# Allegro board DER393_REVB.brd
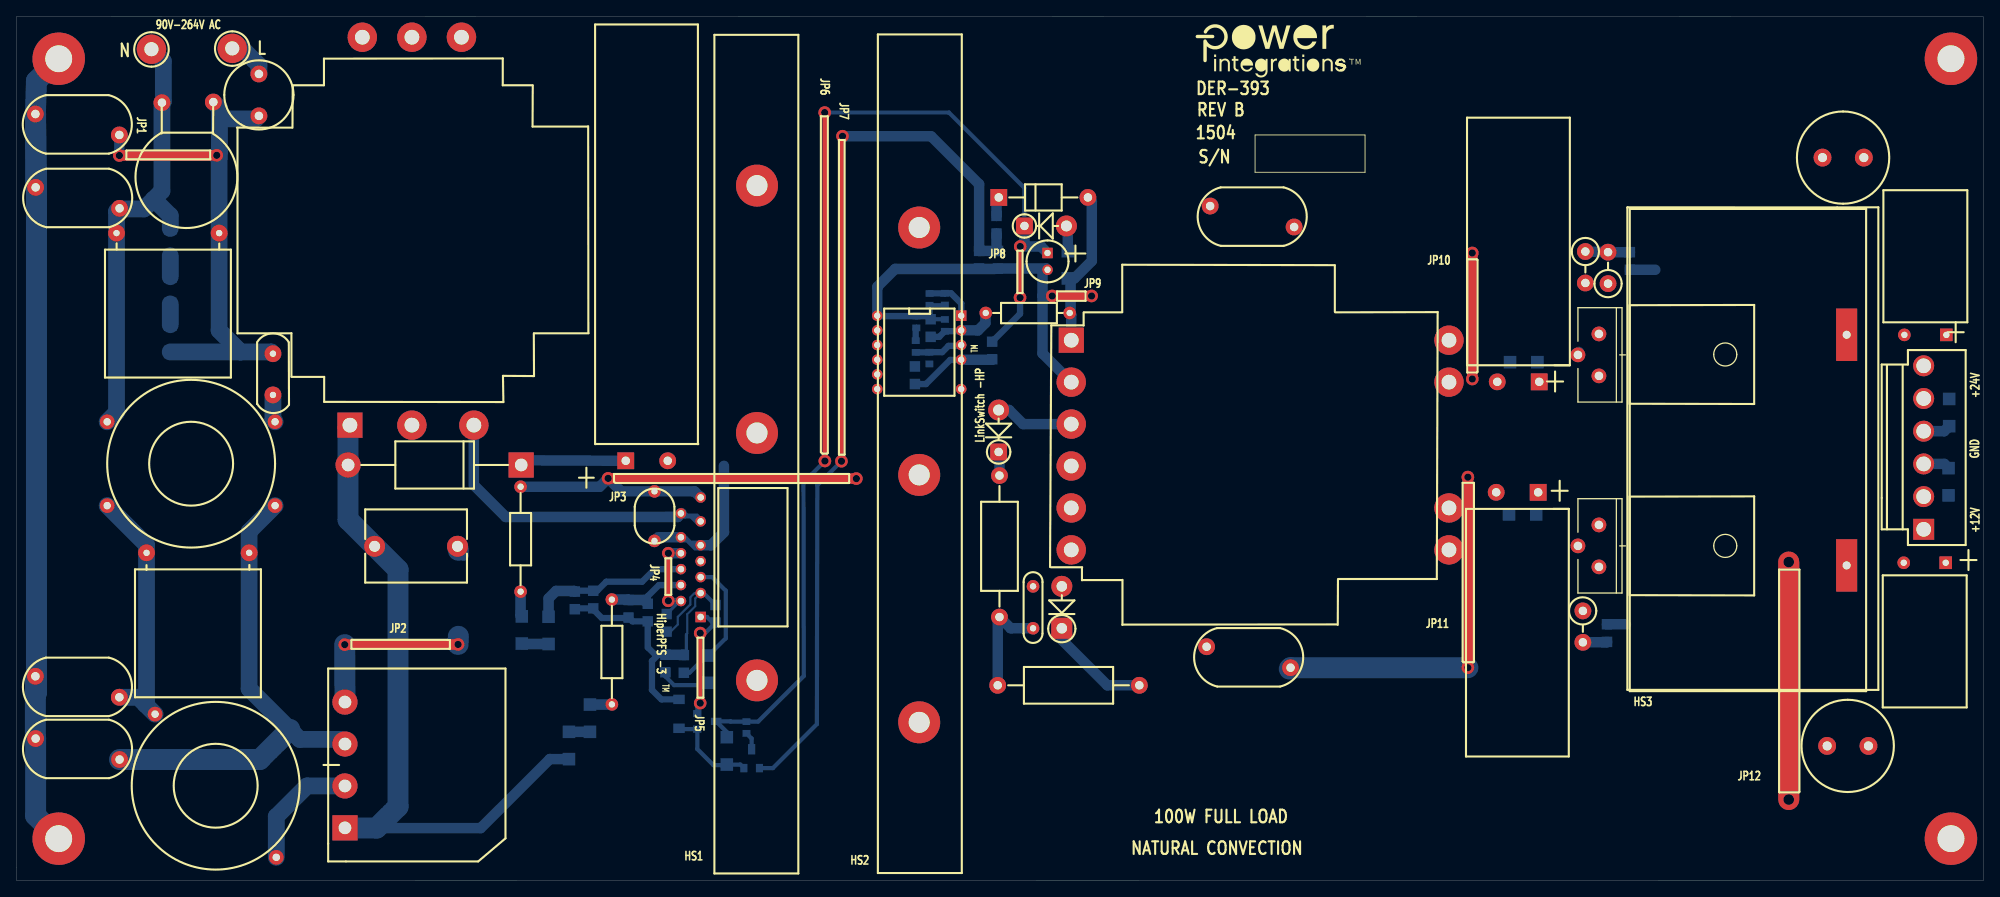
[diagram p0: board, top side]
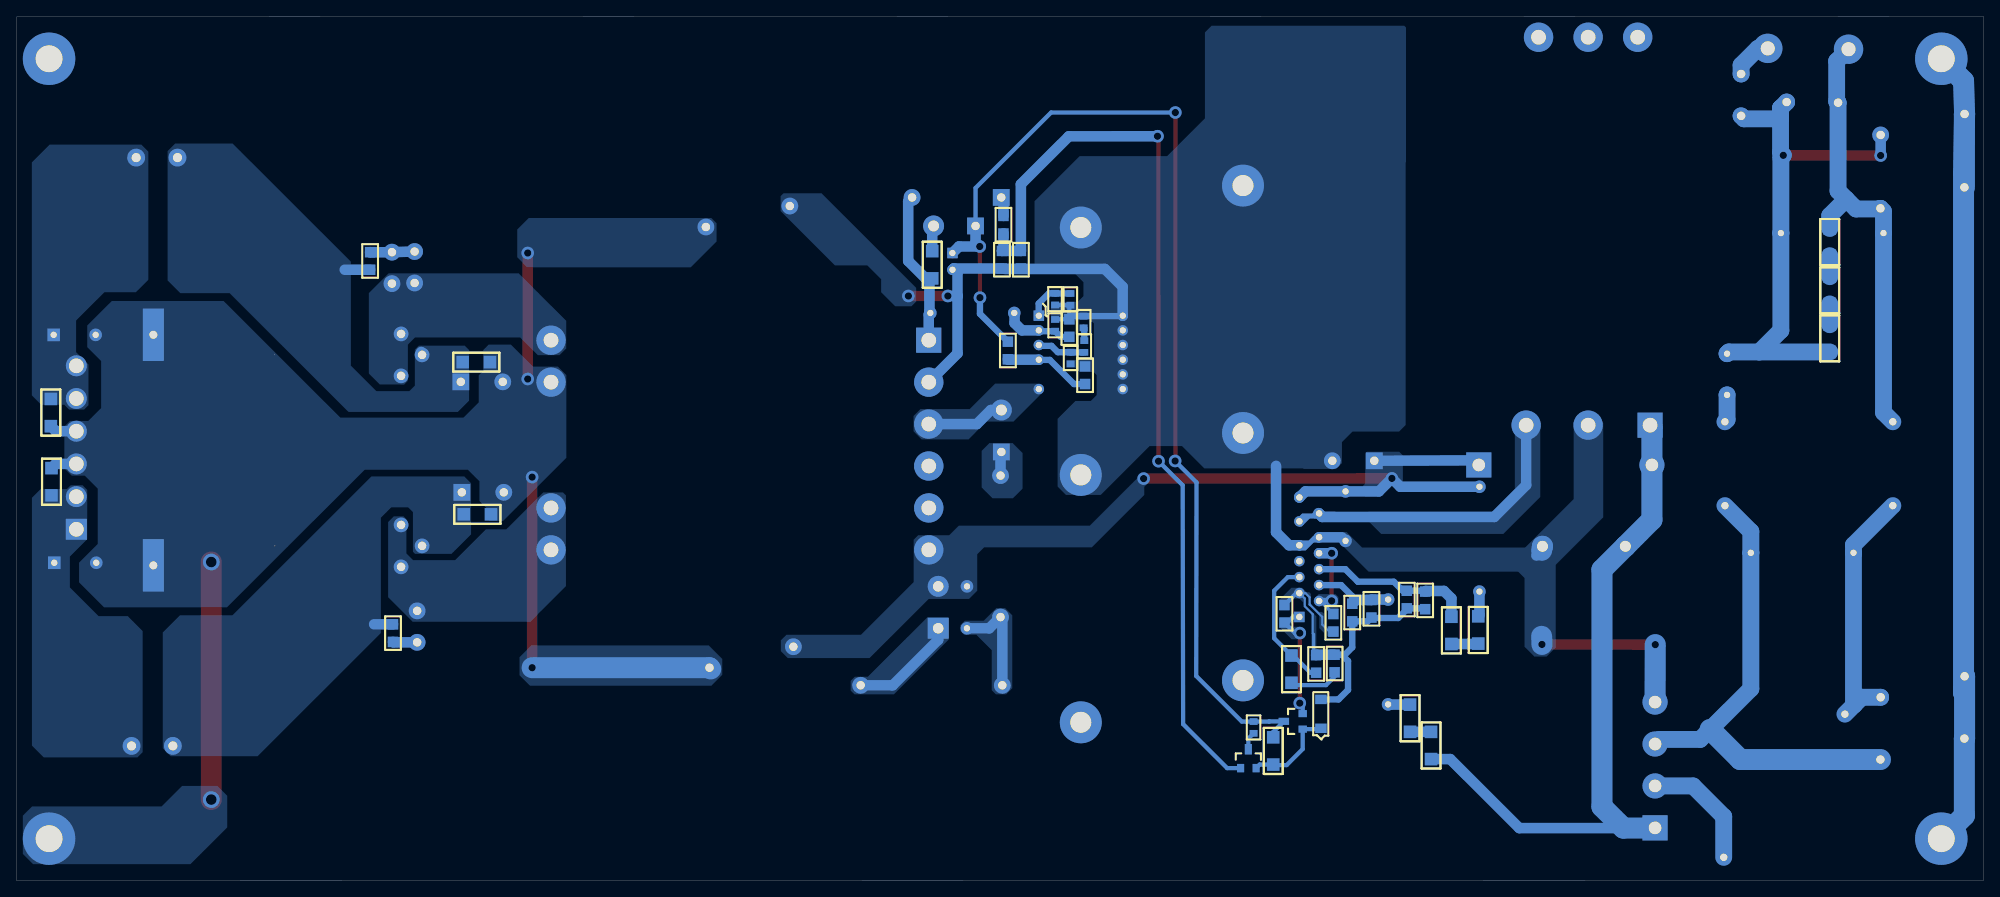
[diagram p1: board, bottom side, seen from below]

Outline 238.07 x 104.67 mm; copper layers: TOP, BOTTOM. Coordinates in mm from the lower left corner of the outline.
Outline path: 0,104.67 238.07,104.62 238.07,0 0,0.03 0,104.67

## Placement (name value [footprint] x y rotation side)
BR1  RS605  [PI_DAX_BRIDGE_RS605_H]  39.75 6.38 90 top
C1  1 nF  [PINPYCAPRAD540X290LS400040]  12.45 90.32 180 top
C2  1 nF  [PINPYCAPRAD540X290LS400040]  2.31 83.97 0 top
C3  220 nF  [PINPCAPRAD550X395490030HORZ]  24.55 78.46 180 top
C4  2.2 nF  [PINPYCAPRAD540X290LS400040]  12.47 14.66 180 top
C5  2.2 nF  [PINPYCAPRAD540X290LS400040]  2.29 24.74 0 top
C6  220 nF  [PINPCAPRAD550X395490030HORZ]  28.18 39.73 180 top
C7  470 nF  [PI_NP_CAPRAD512X345LS394D040]  43.35 40.49 0 bottom
C8  1 uF  [PISMC0805]  84.61 31.24 90 bottom
C9  1 uF  [PISMC0805]  78.69 32.28 270 bottom
C10  470 pF  [PISMC0805]  76.4 33.53 270 bottom
C11  100 nF  [PISMC0805]  80.77 25.17 90 bottom
C12  1 uF  [PISMC0805]  78.54 25.22 90 bottom
C13  10 nF  [PI_NP_CAP250X200LS170D030]  77.22 46.3 270 top
C14  470 pF  [PISMC0805]  69.8 35.1 270 bottom
C15  82 uF  [PI_PCAP_D500LS200_040_2000H]  73.74 50.85 0 bottom
C16  2.2 nF  [PINPCAPRAD350X100200030]  123.04 35.64 270 top
C17  1000 pF  [PISMC0603]  112.37 71.15 270 bottom
C18  100 pF  [PISMC0603]  110.49 64.01 270 bottom
C19  100 nF  [PISMC0603]  108.92 66.95 90 bottom
C20  4.7 uF  [PISMC0805]  108.74 60.15 90 bottom
C21  22  uF  [PIPOLCAPCLYD200LS80030]  124.79 76.02 270 top
C22  *  [PISMC0805]  110.64 65.86 90 bottom
C23  100 nF  [PISMC0805]  118.8 76.28 270 bottom
C24  2.2 nF  [PINPYCAPRAD540X290LS400040]  144.04 28.32 0 top
C25  2.2 nF  [PINPYCAPRAD540X290LS400040]  144.48 81.71 0 top
C26  470 pF  [PISMC0805]  195.28 76.12 270 bottom
C27  1 uF  [PISMC1206]  184.07 62.8 180 bottom
C28  1200 uF  [PIPOLCAPCLYD500LS2000401200LH]  184.3 60.41 180 top
C29  330 uF  [PIPOLCAPCLYD395X630LS200030H]  233.58 66.1 180 top
C30  470 pF  [PISMC0805]  192.51 28.91 90 bottom
C31  1 uF  [PISMC1206]  183.95 44.36 180 bottom
C32  1800 uF  [PIPOLCAPCLYD500LS2000401200LH]  184.18 47.03 180 bottom
C33  470 uF  [PIPOLCAPCLYD395X630LS200030H]  233.5 38.49 180 bottom
D1  1N5408-T  [PIDAX800X225060DO15DO201AD]  61.09 50.34 180 top
D2  FR107-B  [PIDV200X110X040DO41#2]  118.87 51.92 90 top
D3  FR107-B  [PIDV200X110X040DO41#2]  122 79.3 0 top
D4  STPS10150CT  [PIDVTO2203VF1H]  192.04 63.63 270 top
D5  STPS30100ST  [PIDVTO2203VF1H#2]  191.83 40.61 270 top
D6  FR107-B  [PIDV200X110X040DO41]  118.88 82.75 0 top
F1  2 A  [PI_TR5_SUBMIN_FUSE]  29.34 97.71 270 top
HS1  HEATSINK,FAB, W/PINS, PI CUST  [PI_HS_PFS3_LNKHP110W]  89.55 84.16 270 top
HS2  HEATSINK,FAB, W/PINS, PI CUST  [PI_HS_PFS3_LNKHP110W]  109.33 19.19 90 top
HS3  HEATSINK, FAB,W/EYELET, PI CUST  [PI_HS_DIODES_SEC_DER393]  223.88 81.36 180 top
J1  CON6  [PI_HDR_6PIN_LOCK]  230.84 42.54 0 top
L1  10mH  [PI_IND_4P_690X512LS300X200D055]  21.13 50.5 0 top
L2  PQ38  [PI_BOBBIN_PQ38_6P]  47.85 78.66 90 top
L3  470uH  [PI_2P_700X400D055_HORIZ]  24.1 11.48 336.8 top
L4  1.0 uH  [PI_CHOKE_TOK441LS197D043]  218.59 87.58 0 top
L5  1.0 uH  [PI_CHOKE_TOK441LS197D043]  219.15 16.31 0 top
MTG_HOLE4  No 4  [PIMTGHOLE4]  5.11 5.07 0 top
MTG_HOLE5  No 4  [PIMTGHOLE4]  234.14 99.56 0 top
MTG_HOLE6  No 4  [PIMTGHOLE4]  5.11 99.56 0 top
MTG_HOLE7  No 4  [PIMTGHOLE4]  234.14 5.07 0 top
NOREF  -  []  -149.29 55.89 0 top
NOREF#2  -  []  238.07 0 90 top
NOREF#3  -  []  -227.1 -143.13 0 top
NOREF#4  -  []  0 0.03 0 top
NOREF#5  -  []  142.72 103.71 0 top
Q1  MMBT4401LT1G  [PISMSOT23132]  82.4 20.22 90 bottom
Q2  MMBT4401LT1G  [PISMSOT23132]  88.04 13.61 180 bottom
R1  620 k  [PISMR1206]  18.61 64.03 90 bottom
R2  620 k  [PISMR1206]  18.61 69.85 90 bottom
R3  620 k  [PISMR1206]  18.61 75.69 90 bottom
R4  6.2 M  [PISMR1206]  66.87 14.71 90 bottom
R5  6.2 M  [PISMR1206]  69.41 18.01 90 bottom
R6  3.74 M  [PI14WRESD100LS500D030]  72.06 21.34 90 top
R7  162 k  [PISMR0805]  74.08 33.99 270 bottom
R8  10 k  [PISMR1206]  85.97 17.35 270 bottom
R9  30.1 k  [PISMR1206]  83.76 27.25 270 bottom
R10  3.74 M  [PI14WVRESD100LS100D030]  61.01 47.7 270 top
R11  6.2 M  [PISMR1206]  61.15 32 270 bottom
R12  6.2 M  [PISMR1206]  64.4 28.65 90 bottom
R13  162 k  [PISMR0805]  67.58 35 270 bottom
R14  1 k  [PI12WRESD180LS675D040]  135.9 23.65 180 top
R15  4.7  [PI12WRESD180LS675D040]  118.97 31.92 90 top
R16  124 k  [PISMR0603]  110.52 71.12 270 bottom
R17  100 k  [PISMR0603]  108.84 63.98 90 bottom
R18  6.8 k  [PISMR0805]  118.08 63.14 90 bottom
R19  3.3  [PISMR1206]  127.24 76.25 270 bottom
R20  61.9 k  [PI14WRESD100LS400D030]  127.47 68.76 180 top
R21  8.66 k  [PISMR0603]  112.37 66.55 90 bottom
R22  2 k  [PISMR0805]  118.62 80.52 270 bottom
R23  330 k  [PISMR0805]  116.51 76.28 270 bottom
R24  2 k  [PISMR0603]  88.34 19.25 270 bottom
R25  30  [PI12WVRESD180LS150D040]  192.63 72.31 90 top
R26  30  [PI12WVRESD180LS150D040]  189.89 76.2 270 top
R27  15  [PI12WVRESD180LS150D040]  189.59 32.66 270 top
R28  20 k  [PISMR1206]  233.92 58.34 270 bottom
R29  24 k  [PISMR1206]  233.85 49.96 270 bottom
RT1  2.5  [PI_RAD150X300LS200D030]  31.04 63.83 270 top
RV1  320 Vac  [PI_RAD450X550LS300D040_H]  24.68 94.67 180 top
T1  XXXX  [PI_BOBBIN_PQ3812_10P_1800LS]  127.66 40.06 0 top
TP1  CON1  [PITPKEYSTONE125X125]  26.11 100.81 0 top
TP2  CON1  [PITPKEYSTONE125X125]  16.33 100.71 0 top
U1  PFS7524L  [PIICLBENDESIPLG]  82.8 31.93 270 top
U2  LNK6777V  [PI_IC_EDIP_11-12P]  114.34 68.43 270 top
VR1  MMSZ4700T1G  [PI_SM_SOD-123_12]  80.19 18.44 90 bottom
VR2  P6KE150A  [PIDV200X140X050DO15DO204AC]  126.52 30.56 90 top

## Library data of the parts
BR1 = DIODE BRIDGE_1234: alternate symbols: (pi_dax_bridge_rs605_h)
C1 C2 C4 C5 C24 C25 = CAP NP: alternate symbols: (pinpycaprad540x290ls400040h)
C3 C6 = CAP NP: alternate symbols: (pinpcaprad550x395490030horz)
C7-C12 C14 C17-C20 C22 C23 C27 C31 = CAP NP
C13 = CAP NP: tolerance: 20
C15 = CAP POL: alternate symbols: (pi_pcap_d500ls200_040_2000h)
C16 C26 C30 = CAP NP: tolerance: 10
C21 = CAP POL: alternate symbols: (pipolcapclyd200ls80030h)
C28 C32 = CAP POL: alternate symbols: (pipolcapclyd500ls2000401200lh); tolerance: 20
C29 C33 = CAP POL: alternate symbols: (pipolcapclyd395x630ls200030h); tolerance: 20
D1 = DIODE: alternate symbols: (pidax800x225060do15do201ad,pidv300x200x060do14wbead)
D2 D3 D6 = DIODE: alternate symbols: (pidax475x125040do41,pidv200x110x040do41wbead,pidax390x125040do41)
D4 = DS_DUAL_CK_AKA: alternate symbols: (pidvto2203,pidvto2203vf1,pidvto2203vf1h)
D5 = DS_DUAL_CK_A_AC: alternate symbols: (pidvto2203vf1)
F1 = FUSE
HS1 = HS-PI_CUSTOM_0
HS2 = HS-PI_CUSTOM_1
HS3 = HS-PI_CUSTOM2
J1 = CON6
L1 = INDUCTOR_4P_revD: alternate symbols: (pi_4p_700x400d055_horiz)
L2 = BPQ38/6P/GENERIC
L3 = INDUCTOR
L4 L5 = INDUCTOR: tolerance: 0.2
MTG_HOLE4-MTG_HOLE7 = MTG_HOLE_6-32
Q1 Q2 = NPN_BEC
R1-R5 R7-R9 R11-R13 R16-R19 R21-R24 R28 R29 = R
R6 R10 R20 = R: alternate symbols: (pi14wvresd100ls200d030,pi14wresd100ls400d030,pi14wresd100ls500d030)
R14 R25-R27 = R: alternate symbols: (pi12wvresd180ls200d040,pi12wvresd180ls250d040,pi12wresd180ls675d040); tolerance: 5%
R15 = R: alternate symbols: (pi12wvresd180ls200d040,pi12wvresd180ls250d040,pi12wresd180ls675d040)
RT1 = THERMISTOR
RV1 = VARISTOR
T1 = BPQ3812/10P/GENERIC
TP1 TP2 = TESTPOINT
U1 = DEV_HIPERPFS-3-eSIP-16C
U2 = DEV_LNKHP_eDIP_eSOP
VR1 = DIODE_ZENER
VR2 = DIODE_ZENER: alternate symbols: (pidax550x140050do15do204ac)

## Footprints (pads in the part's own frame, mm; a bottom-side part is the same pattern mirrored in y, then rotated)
PI12WRESD180LS675D040
  round 2.032 hole 1.016: 1(0,0) 2(17.145,0)
PI12WVRESD180LS150D040
  round 2.032 hole 1.016: 1(0,0) 2(3.81,0)
PI14WRESD100LS400D030
  round 1.524 hole 0.762: 1(0,0) 2(10.16,0)
PI14WRESD100LS500D030
  round 1.524 hole 0.762: 1(0,0) 2(12.7,0)
PI14WVRESD100LS100D030
  round 1.524 hole 0.762: 1(0,0) 2(12.7,0)
PI_2P_700X400D055_HORIZ
  round 1.778 hole 0.889: 1(-10.16,5.08) 2(10.16,-5.08)
PI_BOBBIN_PQ38_6P
  rect 3.048x3.048 hole 1.778: 1(-23.5,7.501)
  round 3.556 hole 1.778: 2(-23.498,0) 3(-23.498,-7.501) 4(23.5,-5.999) 5(23.5,0) 6(23.5,5.999)
PI_BOBBIN_PQ3812_10P_1800LS
  rect 3.048x3.048 hole 1.778: 1(0,25.4)
  round 3.556 hole 1.778: 2(0,20.32) 3(0,15.24) 4(0,10.16) 5(0,5.08) 6(0,0) 7(45.72,0) 8(45.72,5.08) 9(45.72,20.32) 10(45.72,25.4)
PI_CHOKE_TOK441LS197D043
  round 2.159 hole 1.092: 1(0,0) 2(5.001,0)
PI_DAX_BRIDGE_RS605_H
  rect 3.048x3.048 hole 1.524: 1(0,0)
  round 3.048 hole 1.524: 2(5.08,0) 3(10.16,0) 4(15.24,0)
PI_HDR_6PIN_LOCK
  rect 2.54x2.54 hole 1.778: 1(0,0)
  round 2.54 hole 1.778: 2(0,3.962) 3(0,7.925) 4(0,11.887) 5(0,15.85) 6(0,19.812)
PI_HS_DIODES_SEC_DER393
  rect 2.54x6.35 hole 0.965: 1(2.362,43.18) 2(2.362,15.24)
PI_HS_PFS3_LNKHP110W
  round 5.08 hole 2.54: 1(-0.025,0.076) 2(29.947,0.076) 3(59.919,0.076)
PI_IC_EDIP_11-12P
  rect 1.27x1.27 hole 0.762: 1(0,0)
  round 1.27 hole 0.762: 2(1.778,0) 3(3.556,0) 4(5.334,0) 6(8.89,0) 7(8.89,-10.16) 8(7.112,-10.16) 9(5.334,-10.16) 10(3.556,-10.16) 11(1.778,-10.16) 12(0,-10.16)
PI_IND_4P_690X512LS300X200D055
  round 1.778 hole 0.889: 1(-10.16,5.08) 2(-10.16,-5.08) 3(10.16,-5.08) 4(10.16,5.08)
PI_NP_CAP250X200LS170D030
  round 1.524 hole 0.762: 1(-0.838,0) 2(5.156,0)
PI_NP_CAPRAD512X345LS394D040
  round 2.54 hole 1.321: 1(0,0) 2(10.033,0)
PI_PCAP_D500LS200_040_2000H
  rect 2.032x2.032 hole 1.016: 1(0,0)
  round 2.032 hole 1.016: 2(5.08,0)
PI_RAD150X300LS200D030
  round 2.032 hole 0.762: 1(0,0) 2(4.999,0)
PI_RAD450X550LS300D040_H
  round 2.032 hole 1.016: 1(0.851,0.356) 2(7.074,0.432)
PI_SM_SOD-123_12
  rect 1.143x1.397 smd: 1(0,0) 2(3.505,0)
PI_TR5_SUBMIN_FUSE
  round 2.032 hole 1.016: 1(0,0) 2(5.08,0)
PIDAX800X225060DO15DO201AD
  rect 3.048x3.048 hole 1.524: 1(0,0)
  round 3.048 hole 1.524: 2(20.955,0)
PIDV200X110X040DO41
  rect 2.032x2.032 hole 1.016: 1(0,0)
  round 2.032 hole 1.016: 2(10.795,0)
PIDV200X110X040DO41#2
  rect 2.032x2.032 hole 1.016: 1(0,0)
  round 2.54 hole 1.321: 2(5.08,0)
PIDV200X140X050DO15DO204AC
  rect 2.54x2.54 hole 1.27: 1(0,0)
  round 2.54 hole 1.27: 2(5.08,0)
PIDVTO2203VF1H
  round 1.778 hole 1.016: 1(-2.591,-0.508) 2(-0.051,-3.048) 3(2.489,-0.508)
PIDVTO2203VF1H#2
  round 1.778 hole 1.016: 1(-2.464,-0.305) 2(0.076,-2.845) 3(2.616,-0.305)
PIICLBENDESIPLG
  rect 1.27x1.27 hole 0.787: 1(0,0)
  round 1.27 hole 0.787: 3(-1.93,-2.388) 4(-2.896,0) 5(-3.861,-2.388) 6(-4.826,0) 7(-5.791,-2.388) 8(-6.756,0) 9(-7.722,-2.388) 10(-8.687,0) 11(-9.652,-2.388) 13(-11.582,0) 14(-12.548,-2.388) 16(-14.478,0)
PIMTGHOLE4
  round 6.35 hole 3.251: 1(0,0)
PINPCAPRAD350X100200030
  round 1.524 hole 0.762: 1(0,0) 2(5.08,0)
PINPCAPRAD550X395490030HORZ
  round 2.032 hole 0.762: 1(0.025,0.025) 2(12.446,0.025)
PINPYCAPRAD540X290LS400040
  round 2.032 hole 1.016: 1(0,0) 2(10.16,-2.54)
PIPOLCAPCLYD200LS80030
  rect 1.27x1.27 hole 0.762: 1(0,0)
  round 1.27 hole 0.762: 2(2.032,0)
PIPOLCAPCLYD395X630LS200030H
  rect 1.524x1.524 hole 0.762: 1(0,0)
  round 1.524 hole 0.762: 2(5.08,0)
PIPOLCAPCLYD500LS2000401200LH
  rect 2.032x2.032 hole 1.016: 1(0,0)
  round 2.032 hole 1.016: 2(5.08,0)
PISMC0603
  rect 0.813x0.965 smd: 1(0,0) 2(1.422,0)
PISMC0805
  rect 1.27x1.27 smd: 1(0,0) 2(2.134,0)
PISMC1206
  rect 1.524x1.524 smd: 1(0,0) 2(3.302,0)
PISMR0603
  rect 0.813x0.965 smd: 1(0,0) 2(1.422,0)
PISMR0805
  rect 1.27x1.27 smd: 1(0,0) 2(2.134,0)
PISMR1206
  rect 1.524x1.524 smd: 1(0,0) 2(3.302,0)
PISMSOT23132
  rect 0.864x1.016 smd: 1(-1.88,0) 2(0,0)
  rect 0.864x1.27 smd: 3(-0.94,2.286)
PITPKEYSTONE125X125
  round 3.556 hole 1.702: 1(0,0)

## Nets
12V: C33.1 J1.1 J1.2 L5.2 R29.2
24V: C29.1 J1.5 J1.6 L4.2 R28.1
GND: C24.2 C25.2 C27.2 C28.2 C29.2 C31.2 C32.2 C33.2 HS3.1 HS3.2 J1.3 J1.4 MTG_HOLE7.1 R28.2 R29.1 T1.9
GND_EARTH: C1.2 C2.1 C4.2 C5.1 MTG_HOLE4.1 MTG_HOLE6.1
VBUS: C13.1 C15.1 C16.1 C24.1 D1.1 R10.1 T1.6 U1.16(K) VR2.2
VCC: Q1.1(BASE) Q2.2(EMITTER) R8.2 VR1.1
VCCP: C21.1 D3.1 Q1.3(COLLECTOR) R8.1 R18.2 R24.1
RTN: BR1.4(-DC) C7.2 C13.2 C15.2 C17.2 C18.2 C19.2 C20.2 C21.2 C22.2 C23.2 C25.1 HS1.1 HS1.2 HS2.2 HS2.3 L2.2 R16.2 R21.2 R23.2 T1.2 U1.10(S1) U1.11 U2.7(S7) U2.8 U2.9 U2.10 U2.11 U2.12
VRECT: BR1.1(+DC) C7.1 D1.2 L2.1 R4.1
N03629: BR1.2(AC1) L3.2
N548426: R1.2 R2.1
N561104: C2.2 C3.2 L1.1 R3.2 RV1.2 TP2.1
N565893: F1.1 TP1.1
N762808: C1.1 C3.1 F1.2 R1.1 RT1.1 RV1.1
N766734: BR1.3(AC2) C4.1 C6.1 L1.3
N1756866: C8.2 C9.2 C10.2 C11.2 C12.2 C14.2 R7.2 R13.2 U1.4(G) VR1.2
N1927297: C12.1 R9.2
N1947560: C5.2 C6.2 L1.2 L3.1
N2112567: L2.3 U1.13(D)
N2121451: C10.1 R6.2 R7.1 U1.5(V)
N2121492: C9.1 U1.3(REF) U1.9(PGT)
N2121508: C8.1 Q1.2(EMITTER) U1.1(VCC)
N2122246: C14.1 R12.2 R13.1 U1.7(FB)
N2122529: C11.1 R9.1 U1.6(C)
N2126475: R4.2 R5.1
N2126479: R5.2 R6.1
N2213244: L1.4 RT1.2
N2334561: C16.2 R14.2 R15.1
N2334704: D2.2 T1.3 U2.6(D)
N2334708: D2.1 R15.2
N2334716: C17.1 R16.1 U2.1(PD)
N2334802: C19.1 R17.2
N2334806: C18.1 R17.1 U2.3(CP)
N2334875: C22.1 R20.2 R21.1 U2.2(FB)
N2334923: C20.1 R18.1 U2.4(BP)
N2335058: R14.1 VR2.1
N2335116: D6.2 R19.2 R20.1 T1.1
N2335134: D3.2 R19.1
N2335668: D4.1(A1) D4.3(A2) R25.1 R26.2 T1.10
N2335702: D5.1(A1) D5.3(A2) R27.1 T1.7 T1.8
N2335990: C30.1 R27.2
N2336003: C30.2 C31.1 C32.1 D5.2(K) L5.1
N2336055: C26.1 R25.2 R26.1
N2336076: C26.2 C27.1 C28.1 D4.2(CATHODE) L4.1
N4685146: D6.1 R22.1
N4685154: C23.1 Q2.1(BASE) R22.2 R23.1
N4699564: Q2.3(COLLECTOR) R24.2
N4704043: R2.2 R3.1
N4742949: R10.2 R11.1
N4743334: R11.2 R12.1

Pads without a net: HS1 3; HS2 1; L2 4 5 6; MTG_HOLE5 1; T1 4 5; U1 8 14

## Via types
v1: diameter 1.524, hole 0.889, TOP to BOTTOM, 22 vias
v2: diameter 2.032, hole 1.295, TOP to BOTTOM, 2 vias

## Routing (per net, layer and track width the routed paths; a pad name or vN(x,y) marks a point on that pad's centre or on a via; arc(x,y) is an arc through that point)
GND: length 95.4
  TOP w1.27: v1(176.2,76.02) v1(176.2,60.76) ; v1(175.67,25.78) v1(175.67,48.87)
  TOP w2.54: v2(214.5,38.58) v2(214.5,9.8)
  BOTTOM w1.27: J1.4 233.31,54.43 R28.2 ; J1.3 233.34,50.47 R29.1
  BOTTOM w2.54: 154.05,25.63 C24.2 v1(175.67,25.78)
GND_EARTH: length 109.7
  BOTTOM w2.032: 2.29,84 C2.1
  BOTTOM w2.54: MTG_HOLE6.1 2.41,96.86 C1.2 ; C2.1 2.31,92.84 C1.2 ; C1.2 2.41,85.67 2.41,22.76 C5.1 2.29,17.22 C4.2 2.31,7.86 MTG_HOLE4.1
VBUS: length 66.1
  TOP w1.27: v1(101.65,48.69) v1(71.6,48.72)
  BOTTOM w1.27: D1.1 62.31,50.9 C15.1 ; R10.1 70.59,47.7 v1(71.6,48.72) 73.18,47.14 C13.1 82.07,47.14 U1.16 82.8,46.51
VCC: length 11.3
  BOTTOM w0.508: VR1.1 80.28,18.34 Q1.1 82.4,15.93 84.34,13.98 85.9,13.98 R8.2 87.6,14.05 Q2.2
VCCP: length 137.1
  TOP w0.508: v1(121.49,76.81) v1(121.46,70.61) ; v1(97.82,93.04) 97.82,50.57 v1(97.84,50.83)
  BOTTOM w0.508: D3.1 122,83.9 112.85,93.04 v1(97.82,93.04) ; Q1.3 86.44,19.28 86.46,19.25 R24.1 89.76,19.25 95.29,24.78 95.25,48.22 v1(97.84,50.83) ; Q1.3 85.97,18 R8.1 ; Q1.3 84.66,19.25
  BOTTOM w0.762: v1(121.46,70.61) 121.46,68.66 R18.2
  BOTTOM w1.27: D3.1 122,77.32 v1(121.49,76.81) 124,76.81 C21.1
RTN: length 100.6
  TOP w1.27: v1(130.12,70.82) v1(125.35,70.82) ; v1(39.73,28.58) v1(53.44,28.6)
  BOTTOM w0.508: U1.10 81.84,40.61 81,41.45 80.29,41.45 ; R21.2 112.34,68 C22.2 110.64,69.57 R16.2 112.06,69.7 C17.2
  BOTTOM w0.762: C23.2 118.52,74.14 ; 118.52,74.14 118.47,74.09 ; 118.52,74.14 R23.2 ; U2.12 104.23,68.38 C19.2 110.26,68.38 C22.2
  BOTTOM w1.27: 85.62,50.23 85.62,42.19 84.05,40.61 U1.10 ; 124.64,74.14 124.18,73.69 124.18,70.84 ; 124.64,74.14 C23.2 ; 124.64,74.14 C21.2 ; v1(125.35,70.82) 124.21,70.82 124.18,70.84 ; 118.47,74.09 106.35,74.09 104.19,71.93 104.19,68.44 U2.12 ; 124.18,70.84 124.18,63.86 T1.2 ; 77.65,41.58 U1.11 ; 53.48,40 54.11,39.37
  BOTTOM w2.54: 53.48,29.58 v1(53.44,28.6) ; BR1.4 v1(39.73,28.58) ; C7.2 53.48,40
VRECT: length 83.1
  BOTTOM w1.27: 43.58,6.35 56.18,6.35 64.54,14.71 R4.1
  BOTTOM w2.54: BR1.1 39.8,6.35 43.58,6.35 46.18,8.94 46.18,37.66 C7.1 40.13,43.7 D1.2 40.13,54.94 L2.1
N03629: length 14.8
  BOTTOM w2.032: L3.2 31.44,7.75 35.15,11.46 BR1.2
N548426: length 2.5
  BOTTOM w2.032: R2.1 R1.2
N561104: length 54.8
  BOTTOM w2.032: R3.2 18.61,80.56 16.61,82.55 ; 16.61,82.55 15.42,81.36 12.55,81.36 C2.2 12.1,81.06 C3.2 12.1,56.71 L1.1 ; 16.61,82.55 17.6,83.54 RV1.2 17.77,94.4 17.77,99.27 TP2.1 16.29,100.67
N565893: length 5.1
  BOTTOM w2.032: F1.1 29.34,98.78 27.3,100.81 TP1.1
N762808: length 64.9
  TOP w1.27: v1(12.45,87.83) v1(24.23,87.86)
  BOTTOM w1.27: C1.1 v1(12.45,87.83)
  BOTTOM w2.032: RT1.1 30.83,64.03 27.13,64.03 ; 24.55,93.58 24.55,92.28 28.98,92.28 F1.2 ; 24.55,93.58 24.56,93.57 24.56,88.19 v1(24.23,87.86) 24.52,87.57 C3.1 24.52,66.64 27.13,64.03 ; 24.55,93.58 RV1.1 ; R1.1 27.13,64.03
N766734: length 60
  BOTTOM w2.032: BR1.3 39.19,17.09 34.29,17.09 28.16,23.23 C6.1 28.16,42.28 L1.3
  BOTTOM w2.54: C4.1 29.44,14.66 33.08,18.3
N1756866: length 43.7
  BOTTOM w0.254: C9.2 79.17,30.15 80.04,31.02 80.04,31.95 80.06,31.95 81.51,33.4 81.51,33.43 81.56,33.43 81.56,34.32 82.07,34.82 U1.4 82.14,34.16 82.14,33.22 81.18,32.26 81.18,29.92 81.08,29.82
  BOTTOM w0.381: 81.08,29.82 81.08,27.71 80.72,27.36
  BOTTOM w0.508: U1.4 83.16,34.82 C8.2
  BOTTOM w0.762: VR1.2 78.06,21.94 76.91,23.09 76.91,26.59 77.67,27.36 ; 77.67,27.36 C12.2 ; 77.67,27.36 77.29,27.36 76.4,28.24 C10.2 74.54,31.39 R7.2 74.03,31.8 70.84,31.8 69.8,32.84 C14.2 67.68,32.97 R13.2
  BOTTOM w1.27: C12.2 80.72,27.36 C11.2
N1927297: length 6.3
  BOTTOM w0.508: R9.2 83.48,23.67 79.58,23.67 78.54,24.71 C12.1
N1947560: length 31.3
  BOTTOM w2.032: 15.64,21.28 15.74,21.38 C6.2 15.74,40.65 L1.2 ; 15.64,21.28 14.72,22.2 C5.2 ; 15.64,21.28 L3.1
N2112567: length 36.9
  BOTTOM w0.508: 80.49,44.5 80.87,44.12 81.97,44.12 82.58,43.51 U1.13
  BOTTOM w1.27: 80.49,44.5 80.04,44.04 59.21,44.04 55.35,47.9 L2.3
N2121451: length 10
  BOTTOM w0.762: C10.1 76.4,34.44 77.75,35.79 U1.5
  BOTTOM w1.27: C10.1 75.95,33.99 R7.1 74.03,34.04 R6.2
N2121492: length 11.4
  TOP w0.508: v1(78.89,39.65) v1(78.89,33.88)
  BOTTOM w0.381: 80.26,33.86 C9.1
  BOTTOM w0.508: 78.64,33.63 v1(78.89,33.88)
  BOTTOM w0.762: v1(78.89,33.88) 78.92,33.86 U1.3
  BOTTOM w1.27: U1.9 v1(78.89,39.65)
N2121508: length 14.4
  TOP w0.508: v1(82.75,29.97) v1(82.75,21.49)
  BOTTOM w0.508: v1(82.75,21.49) 82.4,21.13 Q1.2 ; U1.1 83.57,31.93 84.25,31.24 C8.1 83.34,29.97 v1(82.75,29.97)
N2122246: length 19.8
  BOTTOM w0.762: U1.7 77.24,37.72 75.72,36.2 71.37,36.2 70.28,35.1 C14.1 67.68,35.1 R13.1
  BOTTOM w1.27: R12.2 64.4,34.18 65.3,35.07 67.5,35.07 R13.1
N2122529: length 16.3
  BOTTOM w0.508: U1.6 84.2,36.75 85.85,35.1 85.85,29.35 R9.1 83.54,27.25 81.46,25.17 C11.1
N2126475: length 2.5
  BOTTOM w1.27: R5.1 R4.2
N2126479: length 5.4
  BOTTOM w0.762: 69.33,21.29 72.01,21.29 72.03,21.31
  BOTTOM w1.27: R6.1 72.03,21.31 R5.2
N2213244: length 3.4
  BOTTOM w2.032: RT1.2 31.04,55.83 L1.4
N2334561: length 13
  BOTTOM w1.27: R14.2 118.76,31.7 R15.1 120.33,30.56 C16.2
N2334704: length 9.5
  BOTTOM w1.27: D2.2 120.14,57 121.84,55.3 T1.3
N2334708: length 2.9
  BOTTOM w1.27: D2.1 118.97,51.82 R15.2
N2334716: length 5.8
  BOTTOM w0.762: R16.1 112.34,71.12 C17.1 113.11,71.15 114.35,69.9 114.35,68.44 U2.1
N2334802: length 1.6
  BOTTOM w0.762: C19.1 108.84,66.88 R17.2
N2334806: length 5.9
  BOTTOM w0.762: U2.3 114.24,64.77 112.8,64.77 112.04,64.01 C18.1 110.46,63.98 R17.1
N2334875: length 8.6
  BOTTOM w0.762: U2.2 114.24,66.55 R21.1 111.68,65.86 C22.1
  BOTTOM w1.27: R20.2 117.27,68.72 117.27,67.54 116.38,66.65 U2.2
N2334923: length 10.6
  BOTTOM w0.762: C20.1 110.08,60.15 113,63.07 114.31,63.07 U2.4
  BOTTOM w1.27: R18.1 118.03,63.09 U2.4
N2335058: length 13.1
  BOTTOM w1.27: VR2.1 126.52,29.16 132.03,23.65 R14.1
N2335116: length 19.4
  BOTTOM w1.27: T1.1 127.66,68.57 R20.1 127.58,68.87 127.58,72.61 R19.2 128.04,72.95 130.15,75.06 130.15,82.28 D6.2
N2335134: length 3.1
  BOTTOM w1.27: R19.1 127.24,79.13 D3.2
N2335668: length 0.8
  BOTTOM w1.27: T1.10 174.19,65.46
N2335990: length 2.9
  BOTTOM w1.27: C30.1 192.46,28.85 189.59,28.85
N2336003: length 2.5
  BOTTOM w1.27: D5.2 189.04,40.36 ; C30.2 194.79,31.04
N2336055: length 5.4
  BOTTOM w1.27: R26.1 R25.2 195.25,76.1 C26.1
N2336076: length 3.4
  BOTTOM w1.27: C26.2 198.35,73.99 ; 189.09,64.03 D4.2
N4685146: length 2.3
  BOTTOM w1.27: R22.1 118.62,82.49 D6.1
N4685154: length 113.1
  TOP w0.508: v1(99.85,50.8) 99.87,89.6 v1(99.97,90.17)
  BOTTOM w0.508: Q2.1 91.54,13.61 96.87,18.95 96.92,47.89 v1(99.85,50.8)
  BOTTOM w1.27: R22.2 118.62,76.45 C23.1 R23.1 116.51,84.35 110.71,90.16 v1(99.97,90.17)
N4699564: length 2.2
  BOTTOM w0.508: R24.2 88.98,17.2 Q2.3
N4704043: length 2.5
  BOTTOM w2.032: R3.1 R2.2
N4742949: length 3.1
  BOTTOM w1.27: R10.2 61.01,32.14 R11.1
N4743334: length 3.3
  BOTTOM w1.27: R11.2 61.2,28.65 R12.1

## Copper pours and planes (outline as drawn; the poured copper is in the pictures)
12V on BOTTOM: 231.98,47.42 235.15,47.42 236.21,46.37 236.21,16.34 234.77,14.91 223.44,14.91 222.81,15.54 222.81,30.23 224.61,32.03 228.14,32.03 231.62,35.51 231.62,39.24 229.51,41.35 229.51,47.32 230.07,47.88 231.52,47.88
24V on BOTTOM: 235.08,57.63 232.28,57.63 231.7,57.05 229.9,57.05 229.36,57.58 229.36,62.51 230.86,64.01 230.86,67.84 227.43,71.27 223.62,71.27 222.12,72.77 222.12,88.32 222.96,89.15 234.06,89.15 236.22,87 236.22,58.78
GND on BOTTOM: 213.77,11.46 218.03,11.46 220.52,8.97 236.19,8.97 237.31,7.85 237.31,3.23 236.07,1.98 217.02,1.98 212.57,6.43 212.57,10.26
GND on BOTTOM: 153.97,80.26 176.07,80.26 177.47,78.87 177.47,75.51 176.24,74.28 156.48,74.28 153.34,77.42 153.34,79.63
GND on BOTTOM: 152.65,24.92 152.65,26.85 154.28,28.47 175.77,28.47 177.19,27.05 177.19,24.87 175.92,23.6 153.97,23.6
GND on BOTTOM: 172.54,62.26 175.56,62.26 178.23,64.92 180.92,64.92 181.58,64.26 181.58,61.75 182.13,61.2 182.13,57.92 183.97,56.08 198.88,56.08 213,70.21 226.54,70.21 229.51,67.23 229.51,64.62 227.84,62.94 227.84,57.23 229.39,55.68 231.6,55.68 232.28,54.99 232.28,49.94 231.39,49.05 229.82,49.05 228.24,47.47 228.24,40.77 230.5,38.51 230.5,36.12 227.48,33.1 212.6,33.1 195.94,49.76 183.44,49.76 182.04,48.36 182.04,45.97 181.23,45.16 181.23,44.07 180.72,43.56 179.17,43.56 171.53,51.21 171.53,61.24
VBUS on BOTTOM: 144.88,29.77 145.57,29.08 145.57,27.79 144.73,26.95 134.82,26.95 127.66,34.11 122.78,34.11 121.79,35.1 121.79,39.52 120.95,40.36 107.92,40.36 101.57,46.71 101.57,47.7 101.02,48.26 101.02,48.54 101.7,49.23 101.93,49.23 108.17,42.99 124.02,42.99 125.17,41.83 128.93,41.83 129.49,41.27 129.49,36.14 135.86,29.77
VBUS on BOTTOM: 70.71,51.94 74.63,51.94 74.83,51.74 74.83,48.08 75.44,47.47 75.44,47.09 74.85,46.51 73,46.51 71.55,47.96 70.74,47.96 70.28,48.41 70.28,51.51
Net_45 on BOTTOM (solid shape): 81.27,44.46 82.46,44.46 82.85,44.07 82.85,42.9 82.5,42.9 81.51,43.89 80.62,43.89 80.18,43.45 78.45,43.45 78.21,43.69 78.21,44.45 78.23,44.45 78.46,44.68 79.73,44.68 80.11,45.06 80.67,45.06
RTN on BOTTOM (solid shape): 81.66,41.2 83.26,41.2 83.36,41.1 83.36,40.41 82.93,39.98 82.04,39.98 81.08,40.94 80.37,40.94 80.16,41.15 80.16,41.83 80.34,42.01 80.85,42.01
RTN on BOTTOM: 69.94,86.97 69.9,87.01 69.9,103.35 70.1,103.56 93.42,103.56 94.23,102.74 94.23,92.33 98.81,87.76 109.4,87.76 114.86,82.3 114.86,74.55 115.44,73.96 115.44,73.74 115.21,73.51 109.96,73.51 108.94,72.49 108.94,70.76 108.97,70.76 109.63,70.1 112.55,70.1 112.88,69.77 112.88,67.56 111.84,67.56 111.81,67.59 111.51,67.59 111.28,67.36 109.98,67.36 109.96,67.39 109.96,67.69 109.68,67.97 108.15,67.97 107.67,67.49 107.67,63.42 108.03,63.07 110.95,63.07 111,63.02 111,62.15 109.96,62.15 109.41,61.61 107.71,61.61 107.34,61.24 107.34,58.8 108.05,58.09 109.91,58.09 112.06,55.93 112.06,47.73 111.05,46.71 106.85,46.71 100.97,52.59 100.97,52.63 97,52.63 94.3,49.92 82.36,49.92 82.3,49.86 78.36,49.86 77.65,50.57 77.65,53.11 76.38,54.38 70.74,54.38 69.94,55.18
RTN on BOTTOM: 54.41,41.05 54.41,41 55.07,40.34 75.21,40.34 77.09,42.21 78.18,42.21 78.49,41.91 78.49,41.48 74.42,37.41 55.3,37.41 54.48,36.6 53.31,36.6 52.53,37.39 52.53,40.72 52.86,41.05
RTN on BOTTOM: 46.02,55.4 46.02,43.99 51.78,38.24 51.78,28.23 52.88,27.13 54.36,27.13 55.55,28.32 55.55,36.65 56.62,37.72 56.62,39.19 49.61,46.2 49.61,55.5 49.23,55.88 46.51,55.88
RTN on BOTTOM: 145.24,83.26 140.64,83.26 129.18,71.81 129.18,70.13 129.74,69.57 131.72,69.57 133.43,71.27 133.43,72.85 135.1,74.52 139.01,74.52 145.59,81.1 145.59,82.91
N1756866 on BOTTOM: 81.36,27.17 81.36,31.84 81.35,31.86 81.37,31.88 81.37,32.54 81.28,32.54 80.74,32.01 80.75,32 80.75,28 80.12,27.37 80.12,26.99 81.08,26.99 81.26,27.17
N1756866 on BOTTOM: 80.39,30.58 79.32,29.51 78.05,29.51 78,29.57 78,30.71 78.08,30.78 79.48,30.78 79.86,31.17 79.86,32.33 80.06,32.54 80.49,32.54 80.92,32.97 81.08,32.97 81.13,32.92 81.13,32.84 80.39,32.11
N1756866 on BOTTOM: 83.77,35.46 85.22,34.01 85.22,32.72 84.05,32.72 84,32.77 84,33.6 83.44,34.16 82.8,34.16 82.79,34.18 82.79,34.15 82.35,33.71 82.35,33.4 82.12,33.17 82.07,33.17 81.99,33.25 82.02,33.27 82.02,34.19 82.37,34.54 82.42,34.54 82.32,34.65 82.09,34.65 81.69,34.24 81.69,33.38 81.61,33.3 81.43,33.3 81.41,33.32 81.41,34.72 81.61,34.92 81.94,34.92 82.47,35.46
N2112567 on BOTTOM: 72.21,44.7 72.22,44.72 72.24,44.7 74.42,44.7 74.42,43.51 72.9,41.99 58.12,41.99 53.64,46.46 53.64,55.04 53.9,55.3 56.92,55.3 56.72,55.09 56.72,47.32 59.33,44.7
N2121492 on BOTTOM: 80.49,33.22 79.83,33.22 79.2,32.59 78.16,32.59 78.08,32.66 78.08,34.34 78.44,34.7 80.47,34.7 80.92,34.24 80.92,33.66
N2121508 on BOTTOM: 82.73,30.73 83.74,30.73 83.85,30.84 83.85,31.09 83.62,31.32 83.41,31.32 83.31,31.42 83.31,32.61 84.07,31.85 85.17,31.85 85.22,31.9 85.22,30.71 83.74,29.24 82.8,29.24 82.58,29.46 82.58,30.58
N2334561 on BOTTOM: 123.83,30.23 123.83,30.94 123.29,31.47 121.01,31.47 119.48,32.99 118.41,32.99 117.55,32.13 117.55,23.29 118.29,22.56 119.53,22.56 120.04,23.06 120.04,27.91 121.89,29.77 123.37,29.77
N2334704 on BOTTOM: 114.48,60.2 119.62,60.2 122.71,57.11 128.66,57.11 129.5,56.27 129.5,54.42 128.52,53.44 122.83,53.44 122.02,54.25 122.02,54.28 120.7,55.6 117.4,55.6 113.89,59.11 113.89,59.61
N2334708 on BOTTOM: 117.5,52.98 120.27,52.98 120.29,53.01 121.26,52.04 121.26,47.62 119.94,46.3 117.47,46.3 116.31,47.47 116.31,51.79
N2335058 on BOTTOM: 125.32,31.9 127.81,31.9 135.03,24.69 136.6,24.69 137.11,24.18 137.11,23.01 136.65,22.56 131.88,22.56 125.25,29.18 125.25,31.83
N2335668 on BOTTOM: 189.84,65.79 177.11,65.79 174.98,63.65 172.34,63.65 171.54,64.45 171.54,67.81 177.29,73.56 193.04,73.56 195.43,71.17 195.43,61.42 194.11,60.1 191.59,60.1 191.57,60.07 191.16,60.07 190.7,60.53 190.7,64.92
N2335702 on BOTTOM: 171.93,47.02 174.32,47.02 178.79,42.54 181.25,42.54 184.99,38.81 190.07,38.81 190.88,39.62 190.88,43.76 191.24,44.12 192.41,44.12 193.09,43.43 193.09,34.32 190.12,31.34 175.9,31.34 171.58,35.66 171.58,46.66
N2336003 on BOTTOM: 183.06,41.94 183.06,48.13 183.88,48.96 195.11,48.96 211.94,32.13 218.29,32.13 220.37,30.05 220.37,16.03 219.41,15.06 208.89,15.06 193.98,29.97 193.98,43.94 192.71,45.21 190.68,45.21 190.09,44.63 190.09,39.83 189.84,39.57 185.42,39.57
N2336076 on BOTTOM: 197.61,62.38 197.61,74.98 211.91,89.28 218.87,89.28 219.79,88.37 219.79,72.69 218.25,71.16 212.28,71.16 197.89,56.77 184.66,56.77 183.3,58.13 183.3,64.22 183.29,64.24 183.29,64.26 183.82,64.8 189.38,64.8 189.87,64.31 189.87,59.94 190.53,59.28 194.51,59.28

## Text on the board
Ref Des/Silkscreen Top: TM | 90V-264V AC | JP2 | JP3 | JP8 | JP9 | JP11 | JP10 | JP12 | LinkSwitch -HP | GND | +12V | +24V | JP1 | JP4 | HiperPFS -3 | JP5 | JP6 | JP7 | N | L | NATURAL CONVECTION | 100W FULL LOAD | 1504 | DER-393 | REV B | S/N
PEN17: 13   MATERIAL FR4 COPPER 2oz THICKNESS 0.062" | SLOTS and CUT OUT
User.5: FIGURE | SIZE | 30.0 | 31.0 | 35.0 | 38.0 | 40.0 | 43.0 | 50.0 | 51.0 | 52.0 | 60.0 | 67.0 | 70.0 | 100.0 | 128.0 | DRILL CHART: TOP to BOTTOM | ALL UNITS ARE IN MILS | QTY | 33 | 13 | 6 | 22 | 2 | 42 | 4
